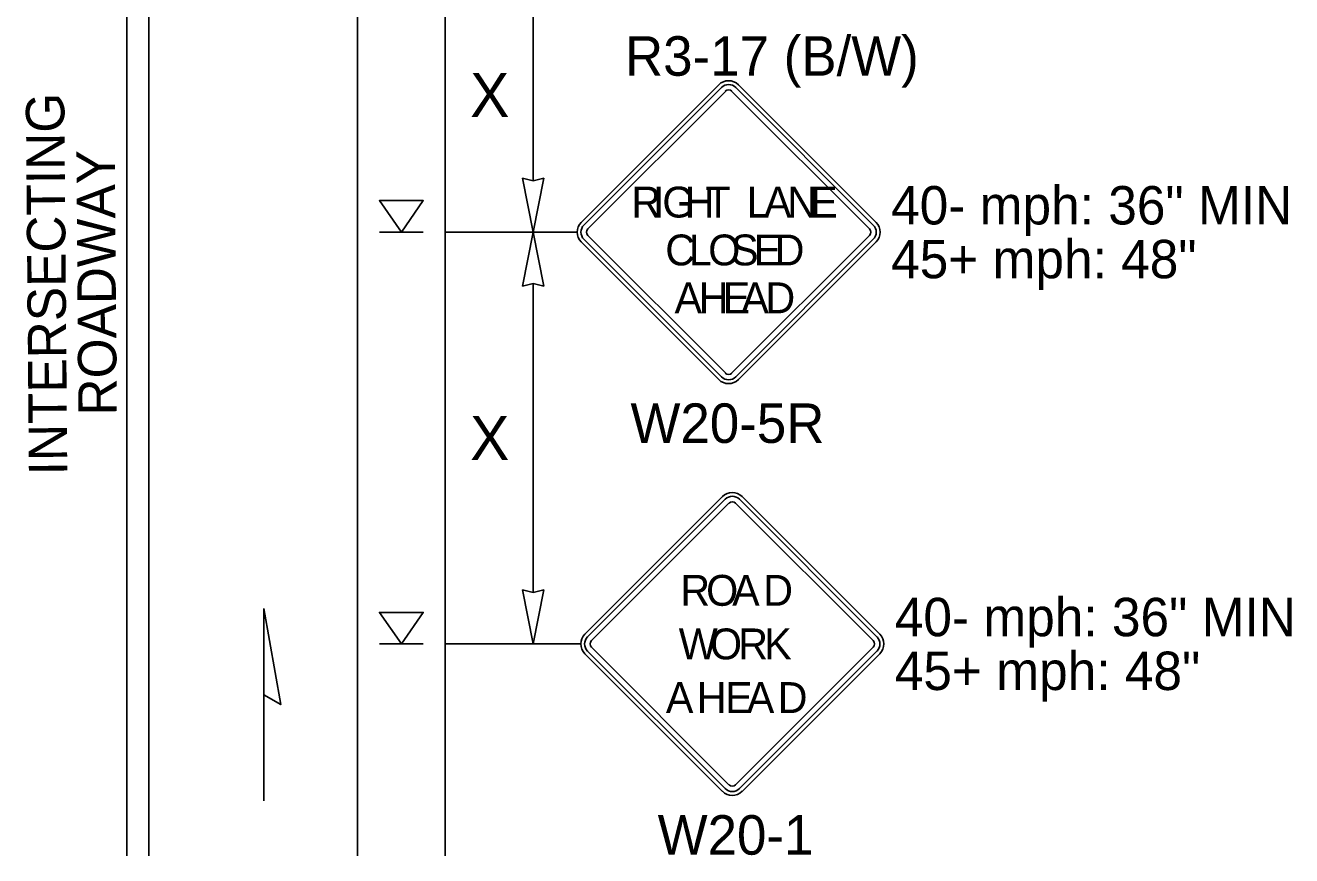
# Model space of a CAD drawing. Extents: x 99958 to 100136, y 99935 to 100013.
# Drawn here: x 100043.467 to 100045.773, y 99971.906 to 99973.418 of the extents above; entities that cross this region are included whole.
import ezdxf

# ---------------------------------------------------------------- set-up
doc = ezdxf.new("R2010")
doc.units = 0
for name, color, linetype in [('RD_ED_ShoulderPavedEdge', 7, 'Continuous'), ('RD_MK_LineDblYellowCenter', 7, 'Continuous'), ('RD_MK_LineEdgeWhite', 7, 'Continuous'), ('SH_DE_DetailBody1Text', 7, 'Continuous'), ('TR_SN_ConstructionSigns', 7, 'Continuous'), ('TR_WZ_PortableSignMountBlk-Org', 7, 'Continuous'), ('TR_WZ_WorkZoneDetails', 7, 'Continuous'), ('TR_WZ_WorkZoneTextCurrent', 7, 'Continuous')]:
    doc.layers.add(name, color=color, linetype=linetype)

msp = doc.modelspace()

# ---------------------------------------------------------------- linework, layer by layer
at = {"layer": 'RD_ED_ShoulderPavedEdge'}
msp.add_lwpolyline([(100044.2319, 99971.9059), (100044.2319, 99973.6724)], dxfattribs=at)
at = {"layer": 'RD_MK_LineDblYellowCenter'}
for p, q in [((100043.6519, 99971.9059), (100043.6519, 99973.5425)), ((100043.6919, 99971.9059), (100043.6919, 99973.5425))]:
    msp.add_line(p, q, dxfattribs=at)
at = {"layer": 'RD_MK_LineEdgeWhite'}
msp.add_line((100044.0719, 99973.6724), (100044.0719, 99971.9059), dxfattribs=at)
at = {"layer": 'TR_SN_ConstructionSigns'}
for p, q in [((100044.7299, 99973.3101), (100044.4794, 99973.0595)), ((100044.7349, 99973.3051), (100044.4843, 99973.0545)), ((100045.0113, 99973.0545), (100044.7608, 99973.3051)), ((100045.0163, 99973.0595), (100044.7657, 99973.3101)), ((100044.4913, 99973.0476), (100044.7419, 99973.2981)), ((100044.7538, 99973.2981), (100045.0044, 99973.0476)), ((100044.4794, 99973.0237), (100044.7299, 99972.7731)), ((100044.4843, 99973.0287), (100044.7349, 99972.7781)), ((100044.7419, 99972.7851), (100044.4913, 99973.0356)), ((100045.0044, 99973.0356), (100044.7538, 99972.7851)), ((100044.7608, 99972.7781), (100045.0113, 99973.0287)), ((100044.7657, 99972.7731), (100045.0163, 99973.0237)), ((100044.7366, 99972.5601), (100044.486, 99972.3095)), ((100044.7416, 99972.5551), (100044.491, 99972.3045)), ((100044.498, 99972.2976), (100044.7485, 99972.5481)), ((100044.7605, 99972.5481), (100045.0111, 99972.2976)), ((100045.018, 99972.3045), (100044.7674, 99972.5551)), ((100045.023, 99972.3095), (100044.7724, 99972.5601)), ((100044.7485, 99972.0351), (100044.498, 99972.2856)), ((100045.0111, 99972.2856), (100044.7605, 99972.0351)), ((100044.486, 99972.2737), (100044.7366, 99972.0231)), ((100044.491, 99972.2787), (100044.7416, 99972.0281)), ((100044.7674, 99972.0281), (100045.018, 99972.2787)), ((100044.7724, 99972.0231), (100045.023, 99972.2737))]:
    msp.add_line(p, q, dxfattribs=at)
for centre, radius, start, end in [((100044.7478, 99973.2922), 0.0253, 45, 135), ((100044.7478, 99973.2922), 0.0183, 45, 135), ((100044.7478, 99973.2922), 0.00844, 45, 135), ((100044.4973, 99973.0416), 0.0253, 135, 225), ((100044.4973, 99973.0416), 0.0183, 135, 225), ((100044.4973, 99973.0416), 0.00844, 135, 225), ((100044.9984, 99973.0416), 0.00844, 315, 45), ((100044.9984, 99973.0416), 0.0183, 315, 45), ((100044.9984, 99973.0416), 0.0253, 315, 45), ((100044.7478, 99972.791), 0.0253, 225, 315), ((100044.7478, 99972.791), 0.0183, 225, 315), ((100044.7478, 99972.791), 0.00844, 225, 315), ((100044.7545, 99972.5422), 0.0253, 45, 135), ((100044.7545, 99972.5422), 0.0183, 45, 135), ((100044.7545, 99972.5422), 0.00844, 45, 135), ((100044.5039, 99972.2916), 0.0253, 135, 225), ((100045.0051, 99972.2916), 0.0253, 315, 45), ((100044.5039, 99972.2916), 0.0183, 135, 225), ((100044.5039, 99972.2916), 0.00844, 135, 225), ((100045.0051, 99972.2916), 0.00844, 315, 45), ((100045.0051, 99972.2916), 0.0183, 315, 45), ((100044.7545, 99972.041), 0.00844, 225, 315), ((100044.7545, 99972.041), 0.0253, 225, 315), ((100044.7545, 99972.041), 0.0183, 225, 315)]:
    msp.add_arc(centre, radius, start, end, dxfattribs=at)
at = {"layer": 'TR_WZ_PortableSignMountBlk-Org'}
for p, q in [((100044.1919, 99973.0416), (100044.1119, 99973.0416)), ((100044.1919, 99972.2916), (100044.1119, 99972.2916))]:
    msp.add_line(p, q, dxfattribs=at)
for points in [[(100044.152, 99973.0416), (100044.1119, 99973.0991), (100044.1919, 99973.0991)], [(100044.152, 99972.2916), (100044.1119, 99972.3491), (100044.1919, 99972.3491)]]:
    msp.add_lwpolyline(points, close=True, dxfattribs=at)
at = {"layer": 'TR_WZ_WorkZoneDetails'}
for p, q in [((100044.3919, 99973.1353), (100044.3919, 99973.4479)), ((100044.2319, 99973.0416), (100044.4719, 99973.0416)), ((100044.3919, 99972.3853), (100044.3919, 99972.9479)), ((100044.2319, 99972.2916), (100044.4786, 99972.2916)), ((100043.9015, 99972.1988), (100043.9015, 99972.0059))]:
    msp.add_line(p, q, dxfattribs=at)
for points in [[(100044.3919, 99973.0416), (100044.3727, 99973.1399), (100044.3919, 99973.1353), (100044.4112, 99973.1399)], [(100044.3919, 99973.0416), (100044.3727, 99972.9433), (100044.3919, 99972.9479), (100044.4112, 99972.9433)], [(100044.3919, 99972.2916), (100044.3727, 99972.3899), (100044.3919, 99972.3853), (100044.4112, 99972.3899)], [(100043.9015, 99972.356), (100043.9323, 99972.181), (100043.9015, 99972.1988)]]:
    msp.add_lwpolyline(points, close=True, dxfattribs=at)

# ---------------------------------------------------------------- texts
at = {"layer": 'SH_DE_DetailBody1Text'}
for s, p in [('INTERSECTING', (100043.5437, 99972.5989)), ('ROADWAY', (100043.6339, 99972.7079))]:
    msp.add_text(s, height=0.07, rotation=90.4626, dxfattribs=at).set_placement(p)
at = {"layer": 'TR_SN_ConstructionSigns'}
for s, p in [('R3-17 (B/W)', (100044.5591, 99973.3265)), ('W20-5R', (100044.5692, 99972.6577)), ('W20-1', (100044.6187, 99971.9077))]:
    msp.add_text(s, height=0.072, rotation=360, dxfattribs=at).set_placement(p)
for s, p in [('R', (100044.5706, 99973.0683)), ('I', (100044.61, 99973.0683)), ('G', (100044.6271, 99973.0683)), ('H', (100044.6679, 99973.0683)), ('T', (100044.7058, 99973.0683)), ('L', (100044.7807, 99973.0683)), ('A', (100044.8122, 99973.0683)), ('N', (100044.8547, 99973.0683)), ('E', (100044.8963, 99973.0683)), ('C', (100044.6325, 99972.9811)), ('L', (100044.6753, 99972.9811)), ('O', (100044.7107, 99972.9811)), ('S', (100044.7523, 99972.9811)), ('E', (100044.7934, 99972.9811)), ('D', (100044.8316, 99972.9811)), ('A', (100044.6494, 99972.8939)), ('H', (100044.6933, 99972.8939)), ('E', (100044.7371, 99972.8939)), ('A', (100044.7709, 99972.8939)), ('D', (100044.8148, 99972.8939)), ('R', (100044.6599, 99972.3611)), ('O', (100044.7069, 99972.3611)), ('A', (100044.7543, 99972.3611)), ('D', (100044.8108, 99972.3611)), ('W', (100044.657, 99972.2635)), ('O', (100044.7139, 99972.2635)), ('R', (100044.7654, 99972.2635)), ('K', (100044.8126, 99972.2635)), ('A', (100044.6336, 99972.1658)), ('H', (100044.6898, 99972.1658)), ('E', (100044.7416, 99972.1658)), ('A', (100044.7809, 99972.1658)), ('D', (100044.8372, 99972.1658))]:
    msp.add_text(s, height=0.0562, dxfattribs=at).set_placement(p)
at = {"layer": 'TR_WZ_WorkZoneDetails'}
for s, p in [('40- mph: 36" MIN', (100045.0437, 99973.0556)), ('45+ mph: 48"', (100045.0437, 99972.9576)), ('40- mph: 36" MIN', (100045.0504, 99972.3056)), ('45+ mph: 48"', (100045.0504, 99972.2076))]:
    msp.add_text(s, height=0.07, dxfattribs=at).set_placement(p)
at = {"layer": 'TR_WZ_WorkZoneTextCurrent'}
for p in [(100044.2772, 99973.2516), (100044.2772, 99972.6266)]:
    msp.add_text('X', height=0.08, dxfattribs=at).set_placement(p)

doc.saveas('drawing.dxf')
